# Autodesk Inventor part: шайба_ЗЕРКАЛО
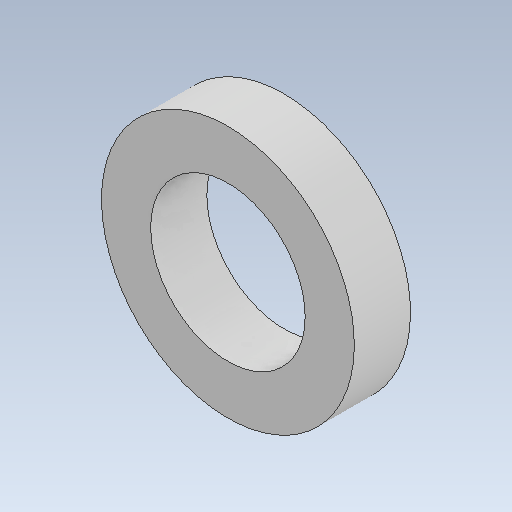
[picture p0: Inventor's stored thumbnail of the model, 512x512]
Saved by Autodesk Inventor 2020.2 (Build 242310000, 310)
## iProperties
Created: 2020-04
Part Number: шайба_ЗЕРКАЛО
Material: Типовые
Document SubType Name: Modeling
Designer: Алексей
Density: 1 g/cm^3
Appearance: По умолчанию
Author: Алексей
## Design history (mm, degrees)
derived "шайба.ipt"
  sketch "Эскиз1"
    geometry: L1 (7, -2)-(-7, -2) reference; C1 r 2.75 at (0, -5) reference; C2 r 4.5 at (0, -5) reference; 1 further point
    dimensions: "d0" = 10 dimension on point (0, 0) C1.centre C1 C2.centre C2 L1.start L1.end L1
feature "Твердое тело1::шайба.ipt" dims "d0" = 10
tag "Элемент создания тегов1"
node "Твердое тело1"
